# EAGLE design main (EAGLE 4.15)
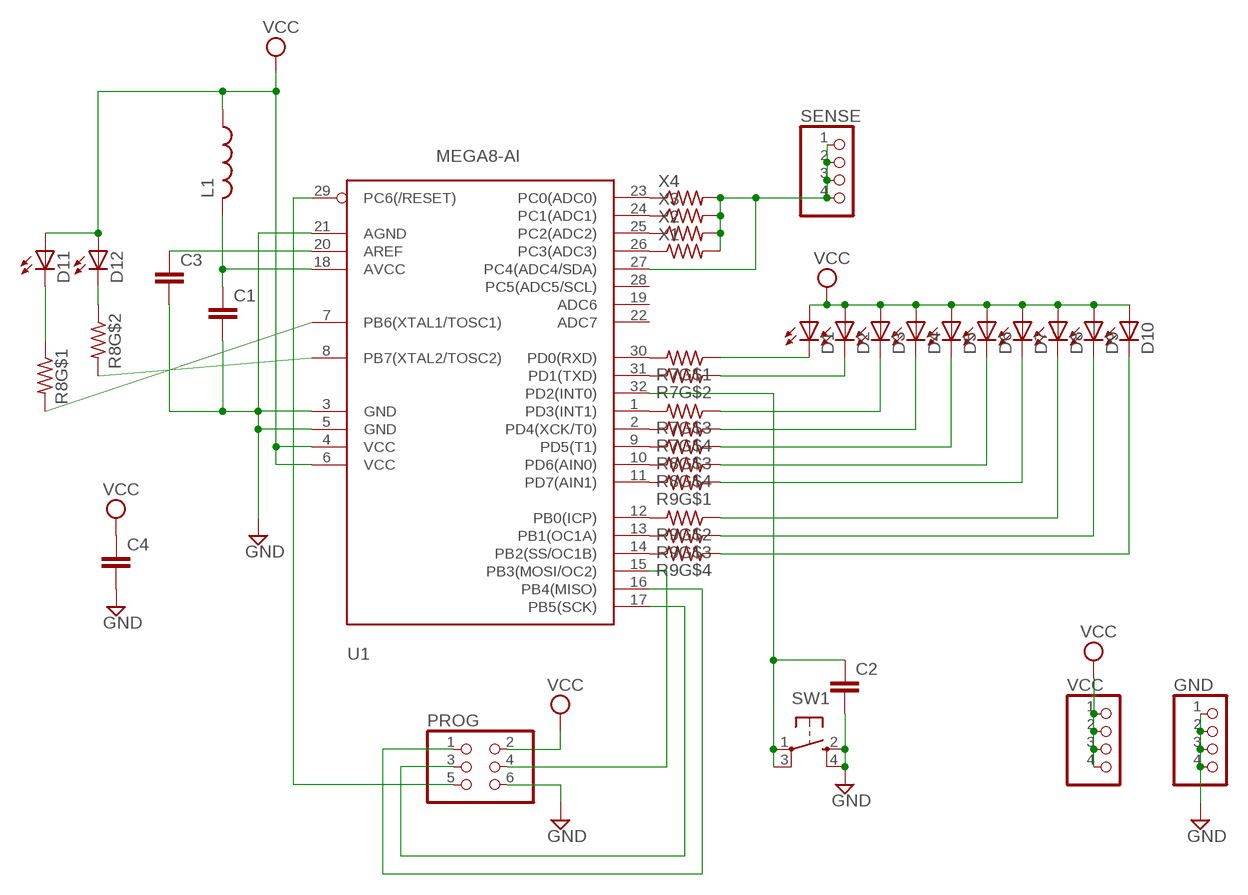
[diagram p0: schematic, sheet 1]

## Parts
C1  C-EUC0805  [C0805]
C2  C-EUC0805  [C0805]
C3  C-EUC0805  [C0805]
C4  C-EUC0805  [C0805]
D1  LEDCHIPLED_1206  [CHIPLED_1206]
D2  LEDCHIPLED_1206  [CHIPLED_1206]
D3  LEDCHIPLED_1206  [CHIPLED_1206]
D4  LEDCHIPLED_1206  [CHIPLED_1206]
D5  LEDCHIPLED_1206  [CHIPLED_1206]
D6  LEDCHIPLED_1206  [CHIPLED_1206]
D7  LEDCHIPLED_1206  [CHIPLED_1206]
D8  LEDCHIPLED_1206  [CHIPLED_1206]
D9  LEDCHIPLED_1206  [CHIPLED_1206]
D10  LEDCHIPLED_1206  [CHIPLED_1206]
D11  LEDCHIPLED_1206  [CHIPLED_1206]
D12  LEDCHIPLED_1206  [CHIPLED_1206]
GND  PINHD-1X4  [1X04]
L1  L-USL0805  [L0805]
PROG  PINHD-2X3  [2X03]
R7  EXB-38V  [EXB-38V]
R8  EXB-38V  [EXB-38V]
R9  EXB-38V  [EXB-38V]
SENSE  PINHD-1X4  [1X04]
SW1  CK_TACTSWITCHJ-LEAD  [CK_KT11_JM]
U1  MEGA8-AI  [TQFP32-08]
VCC  PINHD-1X4  [1X04]
X1  R-US_R0805  [R0805]
X2  R-US_R0805  [R0805]
X3  R-US_R0805  [R0805]
X4  R-US_R0805  [R0805]

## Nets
GND [power]: C1.2 C2.2 C3.2 C4.2 GND.1 GND.2 GND.3 GND.4 PROG.6 SW1.2(S) SW1.4(S1) U1.3(GND) U1.5(GND) U1.21(AGND)
N$1: U1.23(PC0(ADC0)) X4.1
N$2: U1.24(PC1(ADC1)) X3.1
N$3: U1.25(PC2(ADC2)) X2.1
N$4: U1.26(PC3(ADC3)) X1.1
N$5: R7.P$8 U1.30(PD0(RXD))
N$6: R7.P$7 U1.31(PD1(TXD))
N$7: R7.P$6 U1.1(PD3(INT1))
N$8: R7.P$5 U1.2(PD4(XCK/T0))
N$9: R8.P$8 U1.7(PB6(XTAL1/TOSC1))
N$10: R8.P$7 U1.8(PB7(XTAL2/TOSC2))
N$11: R8.P$6 U1.9(PD5(T1))
N$12: R8.P$5 U1.10(PD6(AIN0))
N$13 [power]: C1.1 L1.2 U1.18(AVCC)
N$14: SENSE.1 SENSE.2 SENSE.3 SENSE.4 U1.27(PC4(ADC4/SDA)) X1.2 X2.2 X3.2 X4.2
N$15: PROG.4 U1.15(PB3(MOSI/OC2))
N$16: PROG.3 U1.17(PB5(SCK))
N$17: C2.1 SW1.1(P) SW1.3(P1) U1.32(PD2(INT0))
N$18: PROG.5 U1.29(PC6(/RESET))
N$19: PROG.1 U1.16(PB4(MISO))
N$20: R9.P$8 U1.11(PD7(AIN1))
N$21: R9.P$7 U1.12(PB0(ICP))
N$22: R9.P$6 U1.13(PB1(OC1A))
N$23: R9.P$5 U1.14(PB2(SS/OC1B))
N$25: D1.C R7.P$1
N$26: D2.C R7.P$2
N$27: D3.C R7.P$3
N$28: D4.C R7.P$4
N$29: D5.C R8.P$3
N$30: D6.C R8.P$4
N$31: D7.C R9.P$1
N$32: D8.C R9.P$2
N$33: D9.C R9.P$3
N$34: D10.C R9.P$4
N$36: D11.C R8.P$1
N$37: D12.C R8.P$2
N$38 [power]: C3.1 U1.20(AREF)
VCC [power]: C4.1 D1.A D2.A D3.A D4.A D5.A D6.A D7.A D8.A D9.A D10.A D11.A D12.A L1.1 PROG.2 U1.4(VCC) U1.6(VCC) VCC.1 VCC.2 VCC.3 VCC.4
Unconnected: U1.19(ADC6) U1.22(ADC7) U1.28(PC5(ADC5/SCL))

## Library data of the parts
C1-C4 = proj:C-EU: CAPACITOR, European symbol
D1-D12 = proj:LED: LED
GND SENSE VCC = proj:PINHD-1X4: PIN HEADER
L1 = proj:L-US: INDUCTOR, American symbol
PROG = proj:PINHD-2X3: PIN HEADER
R7-R9 = proj:EXB-38V: Panasonic 4 x 0603 resistor array
SW1 = proj:CK_TACTSWITCH: C&K tactile switches
U1 = proj:MEGA8: MICROCONTROLLER 8 Kbytes FLASH 1 kbytes SRAM 512 bytes EEPROM USART 6-channel 10 bit ADC 2-channel 8 bit ADC
X1-X4 = proj:R-US_: RESISTOR, American symbol

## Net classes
1 power: width 0.305 mm, clearance 0.61 mm

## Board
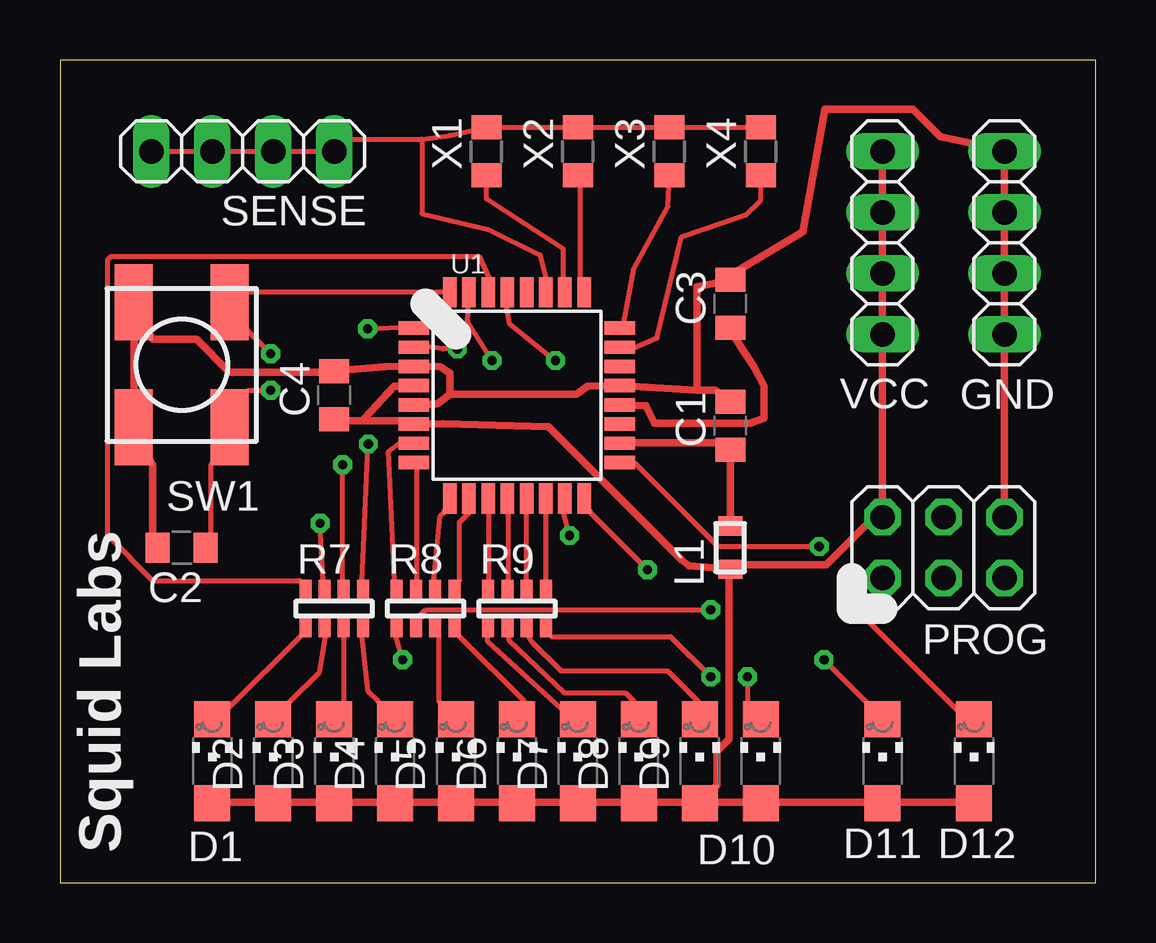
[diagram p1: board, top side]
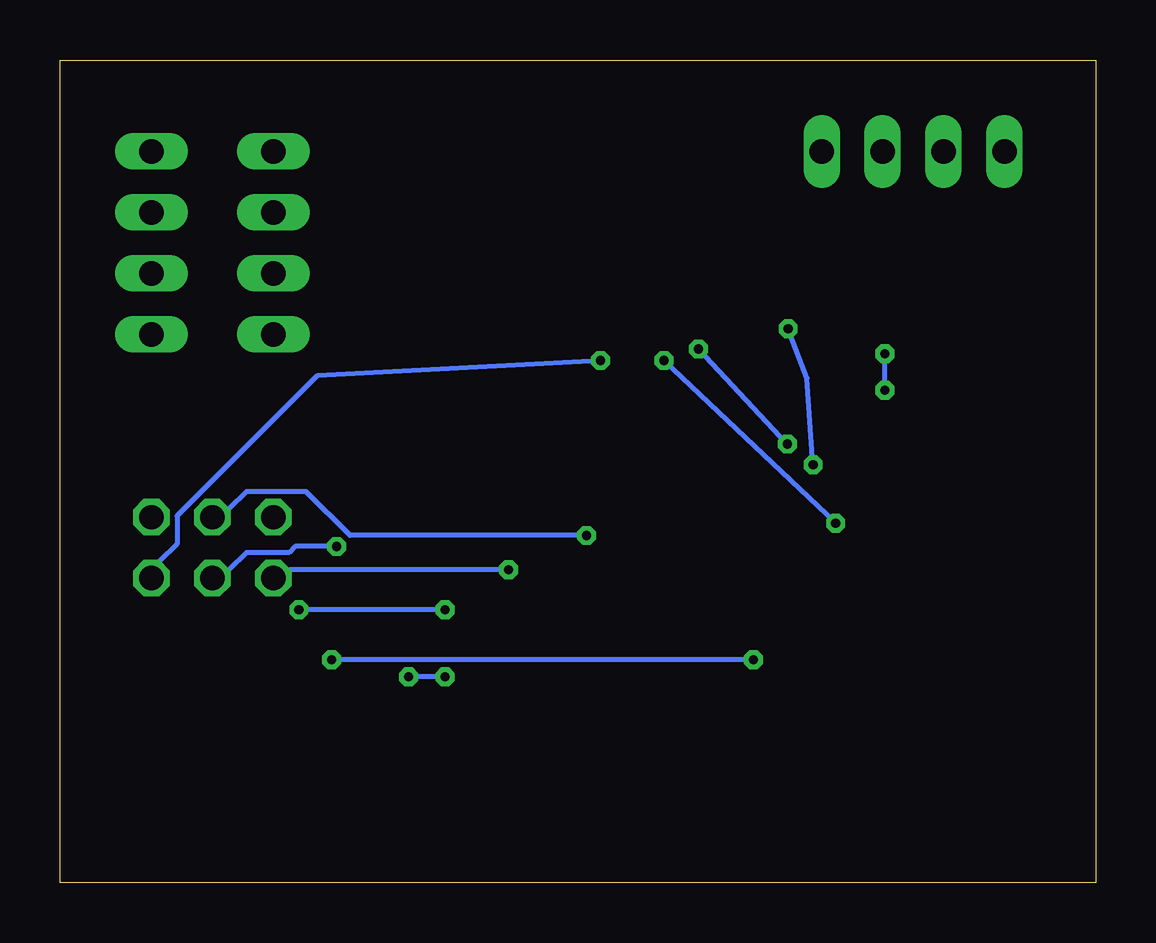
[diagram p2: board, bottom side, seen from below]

Size 43.18 x 34.29 mm. Coordinates in mm from the lower left corner, seen from the top.
Outline: 0,0 43.18,0 43.18,34.29 0,34.29 0,0
Copper layers (1*16): Top 0.035mm / dielectric 1.5mm / Bottom 0.035mm
Design rules "default": minimum track width 8mil, minimum drill 15mil, track to track 8mil, track to pad 8mil, pad to pad 8mil, via to via 8mil, smd to smd 8mil, copper to edge 40mil, drill to drill 8mil, minimum pad ring 10mil, minimum via ring 8mil, stop-mask expansion 4mil, vias tented up to drill 25mil, thermal gap 10mil

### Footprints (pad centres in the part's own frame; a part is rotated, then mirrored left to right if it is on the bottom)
C0805 = smd 1 x 1.25: 1 -1,0; 2 1,0
CHIPLED_1206 = smd 1.5 x 1.5: A 0,-1.75; C 0,1.75
1X04 = drill 1.016 long: 1 -3.81,0; 2 -1.27,0; 3 1.27,0; 4 3.81,0
L0805 = smd 0.8 x 1: 1 -0.9,0; 2 0.9,0
2X03 = drill 1.016 octagon: 1 -2.54,-1.27; 2 -2.54,1.27; 3 0,-1.27; 4 0,1.27; 5 2.54,-1.27; 6 2.54,1.27
EXB-38V = smd 0.5 x 0.8: P$1 -1.2,-0.8; P$2 -0.4,-0.8; P$3 0.4,-0.8; P$4 1.2,-0.8; P$5 1.2,0.8; P$6 0.4,0.8; P$7 -0.4,0.8; P$8 -1.2,0.8
CK_KT11_JM = smd 3.175 x 1.587: 1 -2.603,2; 2 -2.603,-2; 3 2.603,2; 4 2.603,-2
TQFP32-08 = smd 1.27 x 0.559: 1 -4.293,2.8; 2 -4.293,2; 3 -4.293,1.2; 4 -4.293,0.4; 5 -4.293,-0.4; 6 -4.293,-1.2; 7 -4.293,-2; 8 -4.293,-2.8; 17 4.293,-2.8; 18 4.293,-2; 19 4.293,-1.2; 20 4.293,-0.4; 21 4.293,0.4; 22 4.293,1.2; 23 4.293,2; 24 4.293,2.8 | smd 0.559 x 1.27: 9 -2.8,-4.293; 10 -2,-4.293; 11 -1.2,-4.293; 12 -0.4,-4.293; 13 0.4,-4.293; 14 1.2,-4.293; 15 2,-4.293; 16 2.8,-4.293; 25 2.8,4.293; 26 2,4.293; 27 1.2,4.293; 28 0.4,4.293; 29 -0.4,4.293; 30 -1.2,4.293; 31 -2,4.293; 32 -2.8,4.293
R0805 = smd 1 x 1.25: 1 -1,0; 2 1,0

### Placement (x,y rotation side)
C1  27.94,19.05 90 top
C2  5.08,13.97 180 top
C3  27.94,24.13 90 top
C4  11.43,20.32 90 top
D1  6.35,5.08 0 top
D2  8.89,5.08 0 top
D3  11.43,5.08 0 top
D4  13.97,5.08 0 top
D5  16.51,5.08 0 top
D6  19.05,5.08 0 top
D7  21.59,5.08 0 top
D8  24.13,5.08 0 top
D9  26.67,5.08 0 top
D10  29.21,5.08 0 top
D11  34.29,5.08 0 top
D12  38.1,5.08 0 top
GND  39.37,26.67 90 top
L1  27.94,13.97 90 top
PROG  36.83,13.97 0 top
R7  11.43,11.43 0 top
R8  15.24,11.43 0 top
R9  19.05,11.43 0 top
SENSE  7.62,30.48 180 top
SW1  5.08,21.59 270 top
U1  19.05,20.32 0 top
VCC  34.29,26.67 270 top
X1  17.78,30.48 90 top
X2  21.59,30.48 90 top
X3  25.4,30.48 90 top
X4  29.21,30.48 90 top

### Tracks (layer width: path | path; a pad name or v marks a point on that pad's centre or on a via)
GND
  Top 0.305: PROG.6 GND.1 GND.2 GND.3 GND.4 37.9,30.84 36.7,31.09 35.56,32.23 31.88,32.23 30.96,27.13 28.17,25.48 C3.2 27.69,25.2 27.33,24.99 26.54,24.84 26.54,20.52 | C2.2 3.86,14.58 3.86,17.42 SW1.4 3.1,20.52 3.1,22.66 SW1.2 3.86,22.66 5.69,22.66 7.06,21.29 10.82,21.29 C4.2 12.04,21.39 13.54,21.51 U1.3 15.85,21.51 16.26,21.23 16.26,20.37 | 16.26,20.37 15.75,19.96 15.6,19.94 15.34,19.94 U1.5 | 26.54,20.52 24.49,20.65 23.8,20.7 U1.21 22,20.7 21.54,20.37 16.26,20.37 | 26.54,20.52 27.33,20.52 C1.2
N$1
  Top 0.203: X4.1 29.21,28.45 28.6,27.84 25.91,26.92 24.89,22.71 23.93,22.3 U1.23
N$2
  Top 0.203: X3.1 25.35,28.19 23.93,25.6 23.52,23.37 U1.24
N$3
  Top 0.203: X2.1 21.69,29.01 21.69,25.2 U1.25
N$4
  Top 0.203: X1.1 17.78,28.5 20.98,26.42 20.98,25.2 U1.26
N$5
  Top 0.203: R7.P$8 10.01,12.6 3.86,12.6 1.98,14.48 1.98,25.96 2.13,26.11 17.48,26.11 17.88,25.2 U1.30
N$6  (via drill 0.38)
  Top 0.203: v10.85,14.99 10.97,12.6 R7.P$7 | v18.01,21.77 16.99,23.39 U1.31
  Bottom 0.203: v10.85,14.99 v18.01,21.77
N$7  (via drill 0.38)
  Top 0.203: v11.79,17.42 11.79,12.6 R7.P$6 | v12.83,23.09 14.17,23.16 U1.1
  Bottom 0.203: v11.79,17.42 12.04,21.03 v12.83,23.09
N$8  (via drill 0.38)
  Top 0.203: v12.85,18.29 12.6,12.6 R7.P$5 | v16.56,22.25 15.95,22.25 15.34,22.35 U1.2
  Bottom 0.203: v12.85,18.29 v16.56,22.25
N$9
  Top 0.203: R8.P$8 13.95,12.6 13.69,17.98 14.17,18.34 U1.7
N$10
  Top 0.203: R8.P$7 14.88,12.6 14.88,17.27 U1.8
N$11
  Top 0.203: R8.P$6 15.6,12.72 15.85,15.29 16,15.44 U1.9
N$12
  Top 0.203: R8.P$5 16.66,12.6 16.66,15.04 17.07,15.44 U1.10
N$13
  Top 0.305: L1.2 C1.1 27.33,18.34 23.93,18.34 U1.18
N$14
  Top 0.203: SENSE.4 SENSE.3 SENSE.2 SENSE.1 12.14,30.99 15.09,30.99 | X4.2 28.6,31.5 26.01,31.5 X3.2 24.79,31.5 22.2,31.5 X2.2 20.98,31.5 18.39,31.5 X1.2 16.2,31.14 15.09,30.99 | 20.27,25.15 U1.27 | 20.27,25.15 20.27,25.2 | 15.09,30.99 15.09,27.89 17.83,27.23 20.02,26.16 20.27,25.15
N$15  (via drill 0.38)
  Top 0.203: v21.23,14.48 20.98,15.44 U1.15
  Bottom 0.203: v21.23,14.48 31.09,14.48 32.92,16.31 35.41,16.31 36.12,15.6 PROG.4
N$16  (via drill 0.38)
  Top 0.203: v31.65,14.02 27.43,14.02 23.93,17.53 U1.17
  Bottom 0.203: v31.65,14.02 33.38,14.02 33.63,13.77 35.41,13.77 36.12,13.06 PROG.3
N$17  (via drill 0.38)
  Top 0.203: C2.1 6.3,14.58 6.3,17.42 SW1.3 7.82,20.52 v8.79,20.52 | U1.32 16,24.64 7.82,24.64 SW1.1 7.82,23.01 v8.79,22.05
  Bottom 0.203: v8.79,20.52 v8.79,22.05
N$18  (via drill 0.38)
  Top 0.203: v20.65,21.77 18.72,23.32 18.59,24.03 U1.29
  Bottom 0.203: v20.65,21.77 32.46,21.13 38.3,15.29 38.3,14.12 39.01,13.41 PROG.5
N$19  (via drill 0.38)
  Top 0.203: v24.49,13.06 22.1,15.44 U1.16
  Bottom 0.203: v24.49,13.06 33.58,13.06 PROG.1
N$20
  Top 0.203: R9.P$8 17.88,12.6 17.88,15.44 U1.11
N$21
  Top 0.203: R9.P$7 18.69,12.6 18.69,15.44 U1.12
N$22
  Top 0.203: R9.P$6 19.46,12.6 19.46,15.44 U1.13
N$23
  Top 0.203: R9.P$5 20.27,12.6 20.27,15.44 U1.14
N$25
  Top 0.203: R7.P$1 10.01,10.26 7.06,7.32 D1.C
N$26
  Top 0.203: R7.P$2 11.07,10.26 10.82,8.79 9.6,7.57 D2.C
N$27
  Top 0.203: R7.P$3 11.84,10.26 11.84,7.57 D3.C
N$28
  Top 0.203: R7.P$4 12.6,10.26 12.85,7.98 13.26,7.57 D4.C
N$29
  Top 0.203: R8.P$3 15.8,10.26 15.8,7.57 D5.C
N$30
  Top 0.203: R8.P$4 16.66,10.26 19.36,7.57 D6.C
N$31
  Top 0.203: R9.P$1 17.83,10.26 17.83,10.06 20.88,7.26 D7.C
N$32
  Top 0.203: R9.P$2 18.72,10.26 18.72,10.11 21.03,7.92 23.57,7.92 23.93,7.57 D8.C
N$33
  Top 0.203: R9.P$3 19.53,10.26 19.66,10.06 20.88,8.84 25.32,8.84 26.59,7.57 D9.C
N$34  (via drill 0.38)
  Top 0.203: v27.13,8.59 25.45,10.26 20.47,10.26 R9.P$4 | v28.65,8.59 28.65,7.57 D10.C
  Bottom 0.203: v27.13,8.59 v28.65,8.59
N$36  (via drill 0.38)
  Top 0.203: v14.28,9.3 14.02,10.26 R8.P$1 | v31.85,9.3 33.58,7.57 D11.C
  Bottom 0.203: v14.28,9.3 v31.85,9.3
N$37  (via drill 0.38)
  Top 0.203: v27.13,11.38 15.24,11.38 15.04,11.18 15.04,11.02 R8.P$2 | v33.22,11.38 37.39,7.21 D12.C
  Bottom 0.203: v27.13,11.38 v33.22,11.38
N$38
  Top 0.305: C3.1 28.17,22.66 28.93,21.51 29.34,20.73 29.34,19.36 28.75,19.15 24.79,19.15 24.43,19.89 U1.20
VCC
  Top 0.305: D12.A 37.39,3.35 35,3.35 D11.A 33.58,3.35 29.92,3.35 D10.A 28.5,3.35 27.38,3.35 D9.A | D1.A 7.06,3.35 8.18,3.35 D2.A 9.6,3.35 10.72,3.35 D3.A 12.14,3.35 13.26,3.35 D4.A 14.68,3.35 15.8,3.35 D5.A 17.22,3.35 18.34,3.35 D6.A 19.76,3.35 20.88,3.35 D7.A 22.3,3.35 23.42,3.35 D8.A 24.84,3.35 25.96,3.35 D9.A | VCC.1 VCC.2 VCC.3 VCC.4 PROG.2 33.58,14.88 31.95,13.26 28.4,13.26 L1.1 | 12.7,19.25 14.17,19.25 U1.6 15.98,19.13 20.37,19 25.91,13.46 26.21,13.21 L1.1 | 12.7,19.25 12.04,19.25 C4.1 | U1.4 14.17,20.7 13.92,20.7 12.7,19.36 12.7,19.25 | D9.A 27.38,4.06 27.38,5.49 27.89,5.99 27.89,12.7 L1.1

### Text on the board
tPlace: Squid Labs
